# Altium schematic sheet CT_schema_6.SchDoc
size 454 x 430 mm
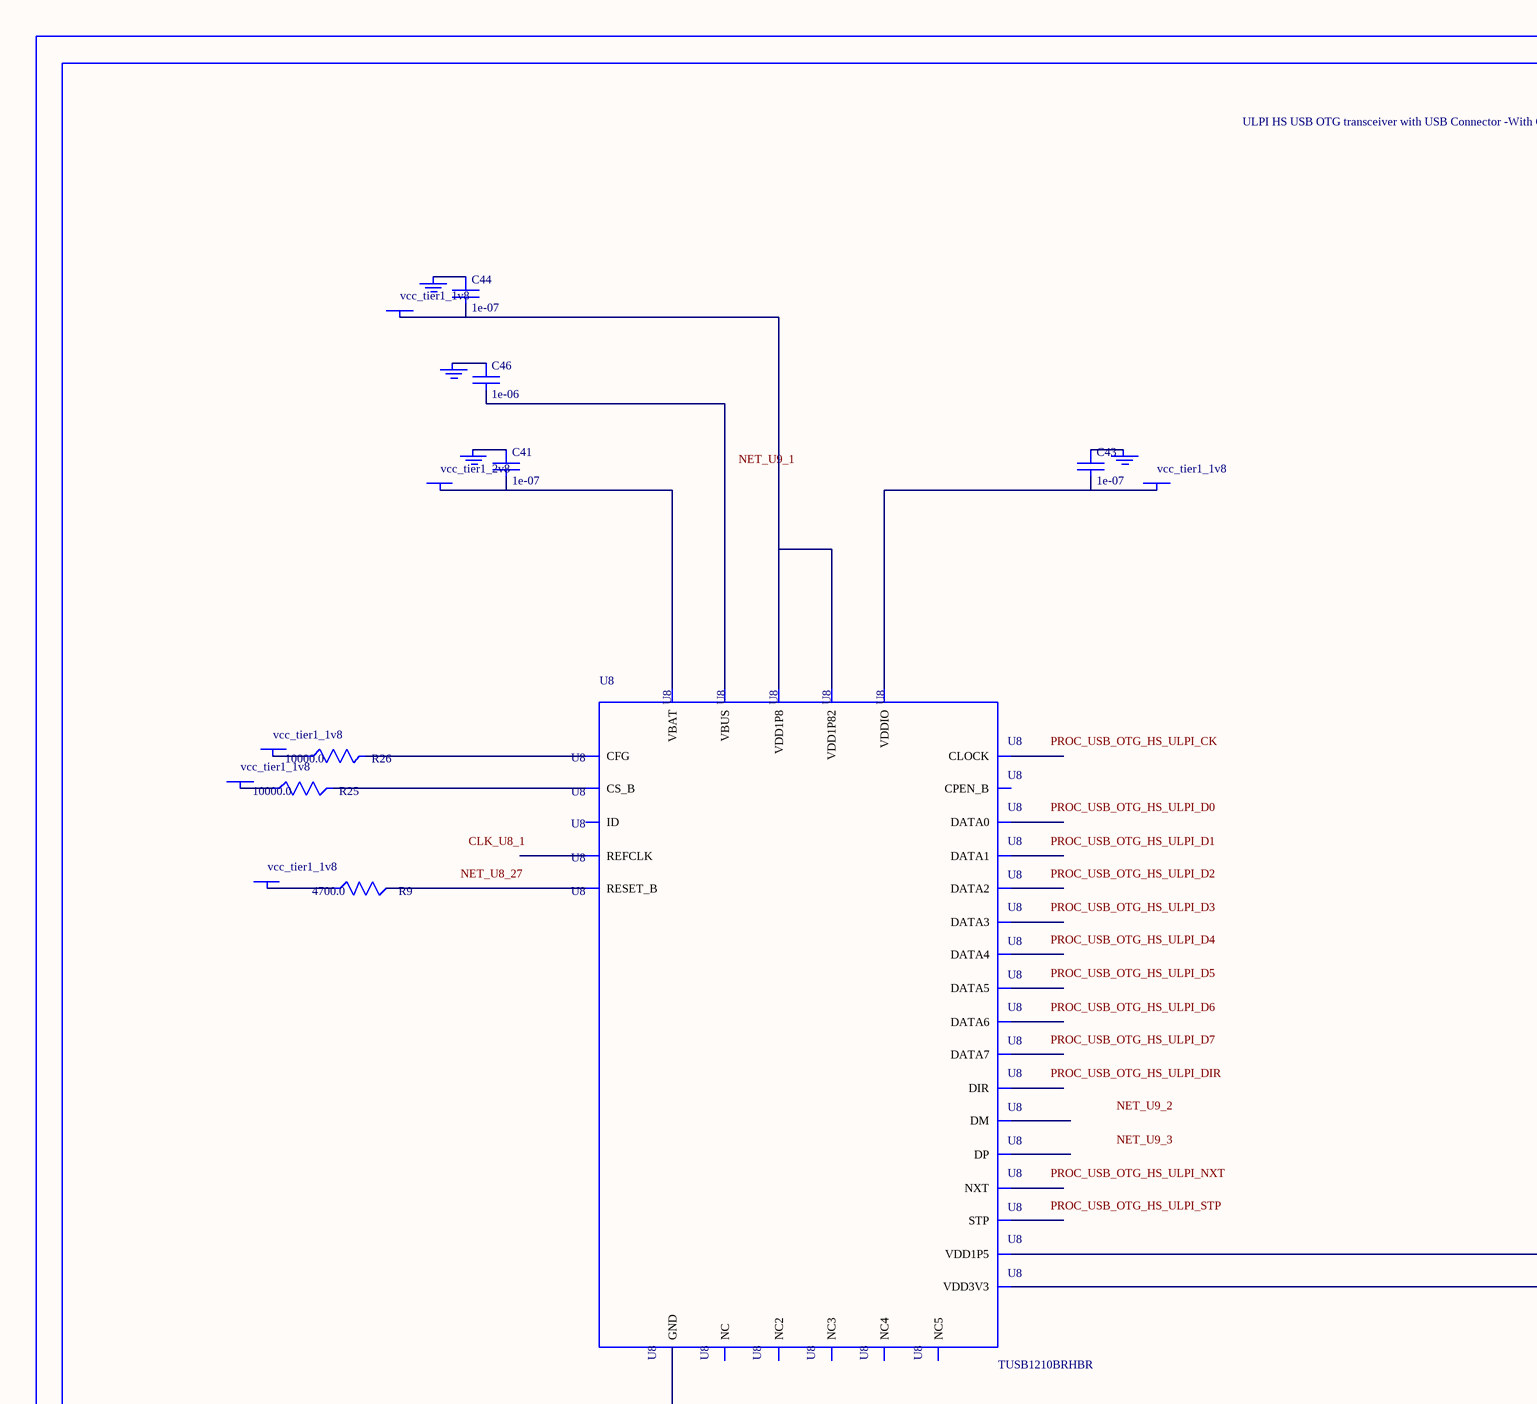
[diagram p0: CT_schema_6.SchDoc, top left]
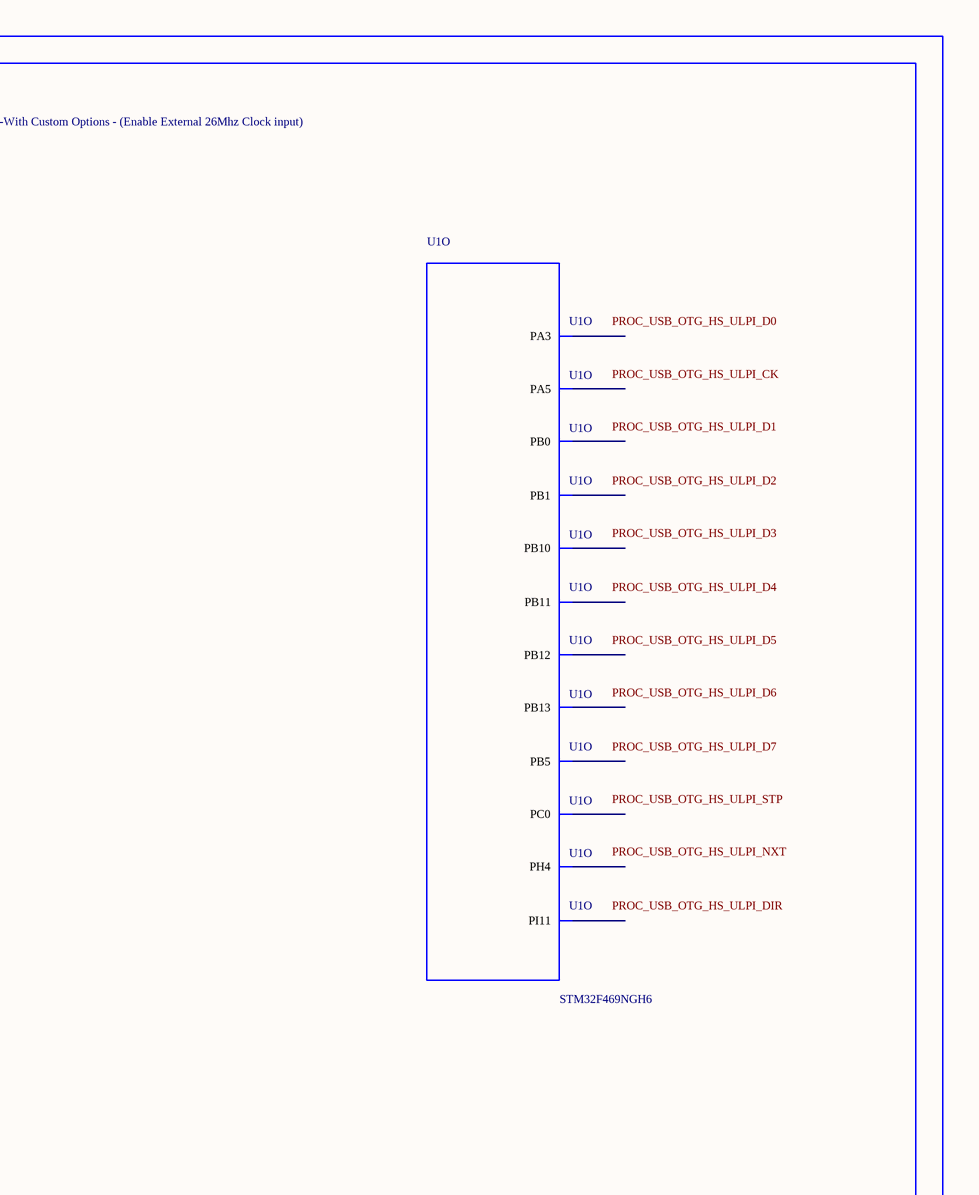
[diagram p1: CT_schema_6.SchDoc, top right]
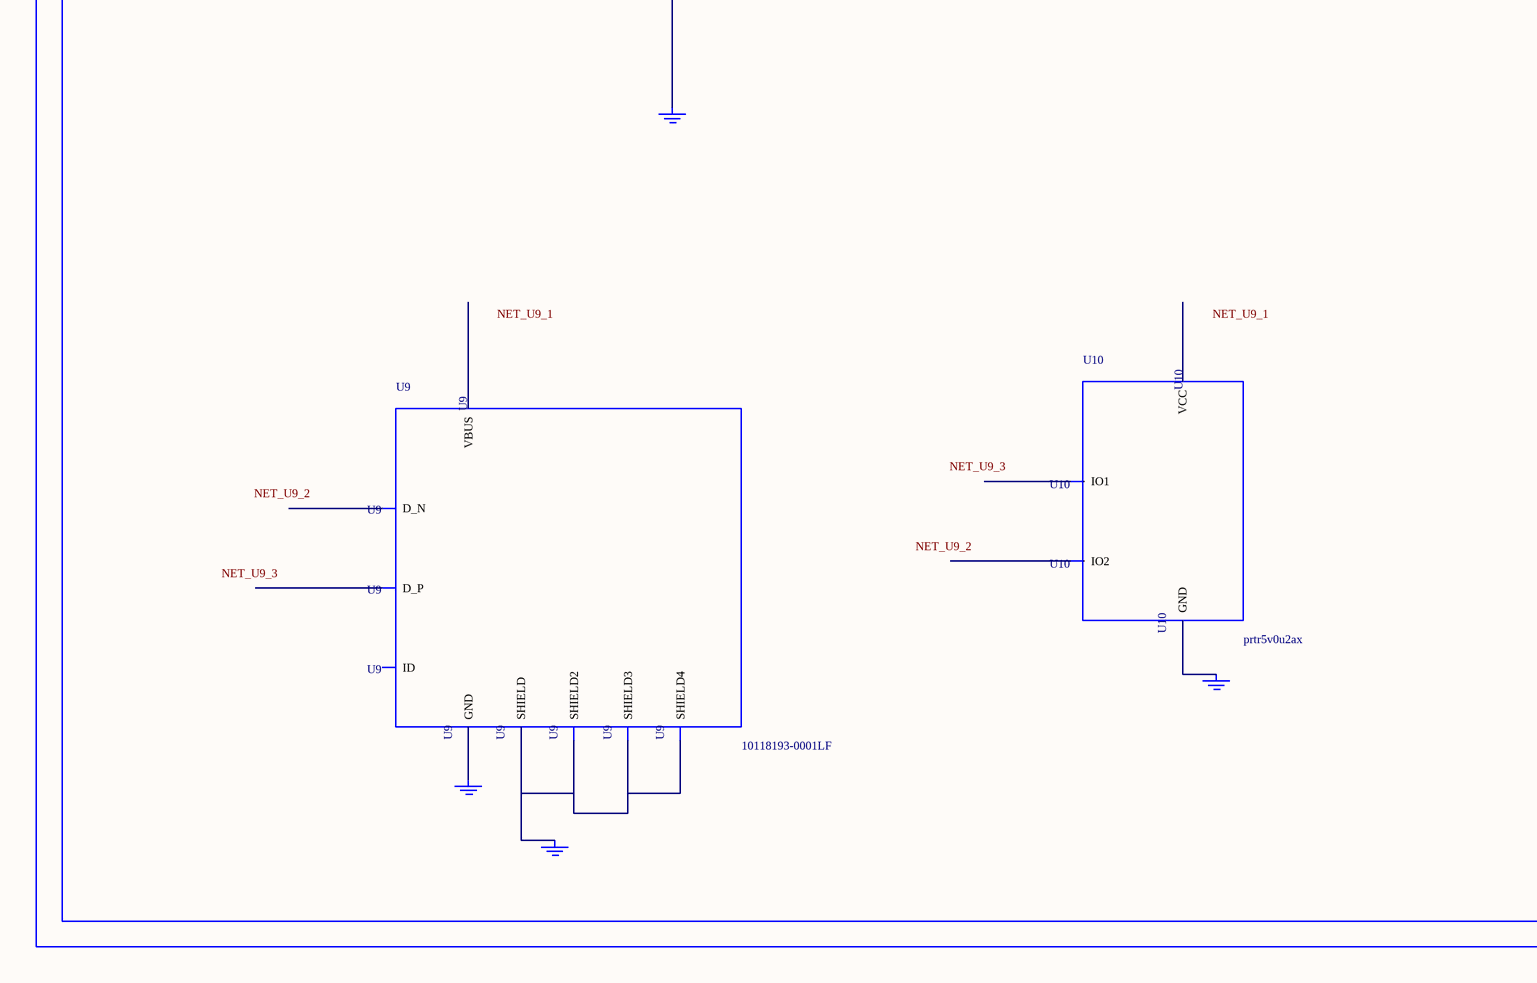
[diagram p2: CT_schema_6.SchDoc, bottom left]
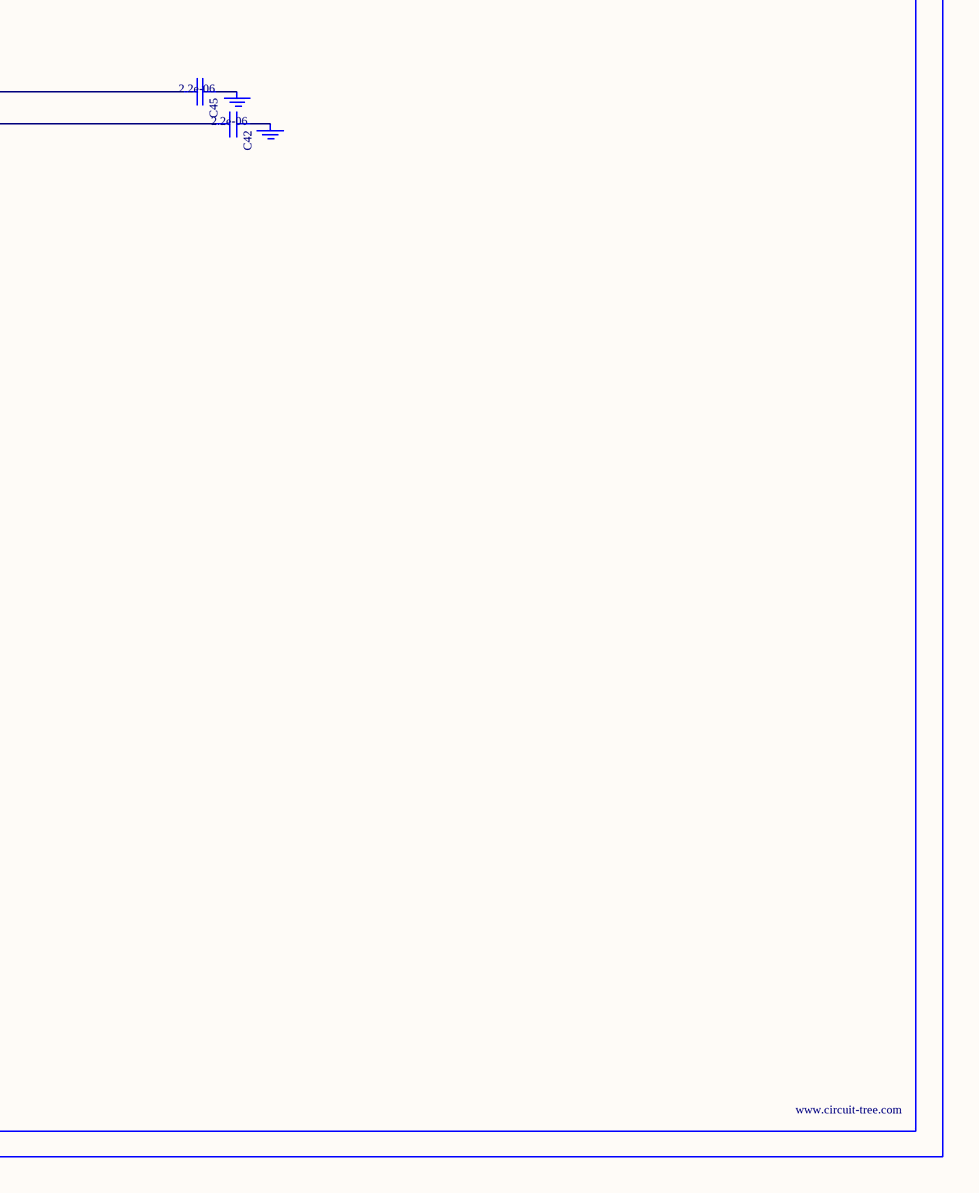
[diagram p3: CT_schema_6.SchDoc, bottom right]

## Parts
BORDER5  (no value)
C41  1e-07  [C0402]
C42  2.2e-06  [C0603]
C43  1e-07  [C0402]
C44  1e-07  [C0402]
C45  2.2e-06  [C0603]
C46  1e-06  [C0603]
GND_INSTANCE_5_0  (no value)
GND_INSTANCE_5_1  (no value)
GND_INSTANCE_5_2  (no value)
GND_INSTANCE_5_3  (no value)
GND_INSTANCE_5_4  (no value)
GND_INSTANCE_5_5  (no value)
GND_INSTANCE_5_6  (no value)
GND_INSTANCE_5_7  (no value)
GND_INSTANCE_5_8  (no value)
GND_INSTANCE_5_9  (no value)
POWER_INSTANCE_5_0  vcc_tier1_1v8
POWER_INSTANCE_5_1  vcc_tier1_1v8
POWER_INSTANCE_5_2  vcc_tier1_2v8
POWER_INSTANCE_5_3  vcc_tier1_1v8
POWER_INSTANCE_5_4  vcc_tier1_1v8
POWER_INSTANCE_5_5  vcc_tier1_1v8
R9  4700.0  [R0603]
R25  10000.0  [R0603]
R26  10000.0  [R0603]
U1  STM32F469NGH6  [TFBGA216]  (part O of 16)
U8  TUSB1210BRHBR  [RHB32_3P45X3P45]
U9  10118193-0001LF  [FCI_10118193-0001LF]
U10  prtr5v0u2ax  [SOT143B]

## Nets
NetC41_1: C41.1 GND_INSTANCE_5_2.0(GND)
NetC41_2: C41.2 POWER_INSTANCE_5_2.0(PWR) U8.21(VBAT)
NetC42_1: C42.1 GND_INSTANCE_5_1.0(GND)
NetC42_2: C42.2 U8.20(VDD3V3)
NetC43_1: C43.1 GND_INSTANCE_5_5.0(GND)
NetC43_2: C43.2 POWER_INSTANCE_5_4.0(PWR) U8.32(VDDIO)
NetC44_1: C44.1 GND_INSTANCE_5_4.0(GND)
NetC44_2: C44.2 POWER_INSTANCE_5_3.0(PWR) U8.28(VDD1P8) U8.30(VDD1P82)
NetC45_1: C45.1 GND_INSTANCE_5_0.0(GND)
NetC45_2: C45.2 U8.12(VDD1P5)
NetC46_1: C46.1 GND_INSTANCE_5_3.0(GND)
NetC46_2: C46.2 U8.22(VBUS)
NetGND_INSTANCE_5_6_0: GND_INSTANCE_5_6.0(GND) U8.33(GND)
NetGND_INSTANCE_5_7_0: GND_INSTANCE_5_7.0(GND) U9.6(SHIELD) U9.7(SHIELD2) U9.8(SHIELD3) U9.9(SHIELD4)
NetGND_INSTANCE_5_8_0: GND_INSTANCE_5_8.0(GND) U9.5(GND)
NetGND_INSTANCE_5_9_0: GND_INSTANCE_5_9.0(GND) U10.1(GND)
NetPOWER_INSTANCE_5_0_0: POWER_INSTANCE_5_0.0(PWR) R25.1
NetPOWER_INSTANCE_5_1_0: POWER_INSTANCE_5_1.0(PWR) R26.1
NetPOWER_INSTANCE_5_5_0: POWER_INSTANCE_5_5.0(PWR) R9.1
NetR9_2: R9.2 U8.27(RESET_B)
NetR25_2: R25.2 U8.11(CS_B)
NetR26_2: R26.2 U8.14(CFG)

Not connected (* = marked no-connect by the designer): U1 A8(PB5) F3(PI11) H4(PH4) K14(PB13) L13(PB12) M2(PC0) P4(PA5) P12(PB10) R2(PA3) R4(PB1) R5(PB0) R13(PB11); U8 1(REFCLK) 2(NXT) 3(DATA0) 4(DATA1) 5(DATA2) 6(DATA3) 7(DATA4) 8(NC) 9(DATA5) 10(DATA6) 13(DATA7) 15(NC2) 16(NC3) 17(CPEN_B) 18(DP) 19(DM) 23(ID) 24(NC4) 25(NC5) 26(CLOCK) 29(STP) 31(DIR); U9 1(VBUS) 2(D_N) 3(D_P) 4(ID); U10 2(IO1) 3(IO2) 4(VCC)

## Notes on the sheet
- Labels drawn without touching a wire or pin: CLK_U8_1, NET_U8_27, NET_U9_1, NET_U9_2, NET_U9_3, PROC_USB_OTG_HS_ULPI_CK, PROC_USB_OTG_HS_ULPI_D0, PROC_USB_OTG_HS_ULPI_D1, PROC_USB_OTG_HS_ULPI_D2, PROC_USB_OTG_HS_ULPI_D3, PROC_USB_OTG_HS_ULPI_D4, PROC_USB_OTG_HS_ULPI_D5, PROC_USB_OTG_HS_ULPI_D6, PROC_USB_OTG_HS_ULPI_D7, PROC_USB_OTG_HS_ULPI_DIR, PROC_USB_OTG_HS_ULPI_NXT, PROC_USB_OTG_HS_ULPI_STP

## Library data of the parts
BORDER5 = BORDER_PAGE5
C41 C43 C44 = C0402C104K3RACTU
C42 C45 = C0603C225K8RACTU
C46 = C0603C105K3RACTU
GND_INSTANCE_5_0-GND_INSTANCE_5_9 = GND
POWER_INSTANCE_5_0-POWER_INSTANCE_5_5 = PWR
R9 = RC0603JR-074K7L
R25 R26 = RC0603JR-0710KL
